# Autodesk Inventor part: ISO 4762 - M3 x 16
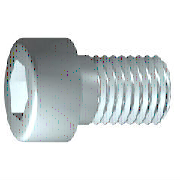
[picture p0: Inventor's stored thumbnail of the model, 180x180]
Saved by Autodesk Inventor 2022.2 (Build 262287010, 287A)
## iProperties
Created: 2021-02
Part Number: ISO 4762 - M3 x 16
Material: Stainless Steel, 440C
Description: Hexagon Socket Head Cap Screw
Document SubType Name: Modeling
Standard: ISO 4762
Designer: Fabian Trauzettel
Standard Revision: Fourth edition 2004-03-01
Standards Organization: ISO
Language: en-US
Size Designation: M3 x 16
Categories: <MemberInstance><Categories><Category DisplayName="Fasteners" InternalName="e4da775c-781d-43d5-af7c-5136215cf5a6" Mnemonic="FSTN"><Category DisplayName="Bolts"
Density: 7.75 g/cm^3
Appearance: Semi-Polished
IsCustomPart: 0
Author: Fabian Trauzettel
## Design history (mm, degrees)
sketch "Sketch1"
  geometry: L1 (-0.867, 0)-(16, 0); L2 (16, 0)-(16, 1.5); L3 (16, 1.5)-(1.25, 1.5); L4 (1.25, 1.5)-(0.943, 1.5); L5 (0.943, 1.5)-(0, 1.5); L6 (0, 1.5)-(0, 2.75); L7 (0, 2.75)-(-3, 2.75); L8 (-3, 2.75)-(-3, 1.443); L9 (-3, 1.443)-(-1.7, 1.443); L10 (-1.7, 1.443)-(-0.867, 0); L11 (-6.8, 0)-(19.8, 0) reference; L12 (0, -0.55)-(0, 3.3) reference; L13 (1.25, 1.5)-(0, 1.5)
  constraints: 22 end point, 6 parallel, 2 collinear, 2 perpendicular, 1 horizontal, 1 point on line
  dimensions: "d1" = 14.75 distance from line of L3.end L2 (= GEL); "d2" = 0.30683 distance of L4.end L3.end (computed from GAL); "d3" = 3 distance between parallel lines of L8 L6 (= KOH); "d4" = 1.3 distance of L8.end L9.end (= INTI); "d5" = 60 deg angle of L10 L1; "d6" = 3 diameter of L3 L1 (= GD); "d7" = 3 diameter of L5 L1 (= BDM); "d8" = 2.88675 diameter of L9 L1 (= 1.1547 x SW); "d9" = 5.5 diameter of L7 L1 (= KOD); "d26" = 16 distance between parallel lines of L12 L2 (= NLG)
revolve "Body" sketch "Sketch1" stored, may be unused: angle "d10" = 90 deg
sketch "Sketch2"
  geometry: L1 (0, -3.85)-(0, 3.85) reference; L2 (-3.85, 0)-(3.85, 0) reference; L3 (1.443, 0)-(0.722, -1.25); L4 (0.722, -1.25)-(-0.722, -1.25); L5 (-0.722, -1.25)-(-1.443, 0); L6 (-1.443, 0)-(-0.722, 1.25); L7 (-0.722, 1.25)-(0.722, 1.25); L8 (0.722, 1.25)-(1.443, 0); 2 further points
  constraints: 12 end point, 1 coincident, 1 horizontal alignment, 1 point on line, 12 other
extrude "Slot" join sketch "Sketch2" stored distance "d11" = 10; taper "d12" = 0 deg
workplane "Work Plane1"
fillet "Fillet2" dims "d30" = 0.1 (= R)
body "Solid1"
fillet "Fillet1" dims "d17" = 0.3 (= RR)
feature "Thread" dims "d13" = 14.75 (= GEL), "d14" = 0
chamfer "Chamfer1" distance "d15" = 0.30673 (= -0.5 x SPD + 0.5 x GD); stored, may be unused: second distance "d16" = 0.30673 (= GUL), angle "d27" = 45 deg
other parameters: "GD" = 3 [user parameter; used in 2 equation terms], "NLG" = 16 [user parameter; used in 1 equation term], "GEL" = 14.75 [user parameter; used in 2 equation terms], "KOD" = 5.5 [user parameter; used in 1 equation term], "KOH" = 3 [user parameter; used in 1 equation term], "INTI" = 1.3 [user parameter; used in 1 equation term], "GAL" = 0.30673 (= 0.61345 x PTC) [user parameter; used in 1 equation term], "GUL" = 0.30673 (= 0.61345 x PTC) [user parameter; used in 1 equation term], "BDM" = 3 (= NND) [user parameter; used in 1 equation term], "SW" = 2.5 [user parameter; used in 2 equation terms], "RR" = 0.3 [user parameter; used in 1 equation term], "SPD" = 2.38655 (= NND - 1.2269 x PTC) [user parameter; used in 1 equation term], "d19" = 0, "d28" = 0, "d29" = 0, "R" = 0.1 [user parameter; used in 1 equation term], "TOA" = 30 deg [user parameter], "GD1" = 2.38655 (= THREADDIA - 1.2269 x PTC) [user parameter], "THREADDIA" = 3 [user parameter; used in 1 equation term], "FAWI" = 45 deg [user parameter], "PTC" = 0.5 [user parameter; used in 5 equation terms], "NND" = 3 [user parameter; used in 2 equation terms], "E0" = 2.8875 (= 1.155 x SW) [user parameter]
